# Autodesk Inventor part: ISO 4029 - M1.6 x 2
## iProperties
Comments: To add or edit properties for Autodesk Inventor files, use iProperties.
Created: 2004-08
Part Number: ISO 4029 - M1.6 x 2
Vendor: Autodesk Inc.
Document SubType Name: Modeling
Designer: John Blackburn
Material: Default
Description: Hexagon Socket Set Screw
Standard: ISO 4029
Alert: To add or edit properties for Autodesk Inventor files, use iProperties.
Control State: 0
Master: False
Checked Out: False
Shininess: 64.0
Length Units: 11269
Angle Units: 11279
Time Units: 11290
Mass Units: 11283
Length Display Precision: 3
Angle Display Precision: 2
Compacted: True
EGR: 1
Density: 0.0
Volumn: 0.0
Area: 0.0
PropertySet Name: Model Information
Author: John Blackburn
Revision Number: 8
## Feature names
1. Body [Revolution]
2. Slot [Extrusion]
3. Chamfer1
4. Chamfer2
